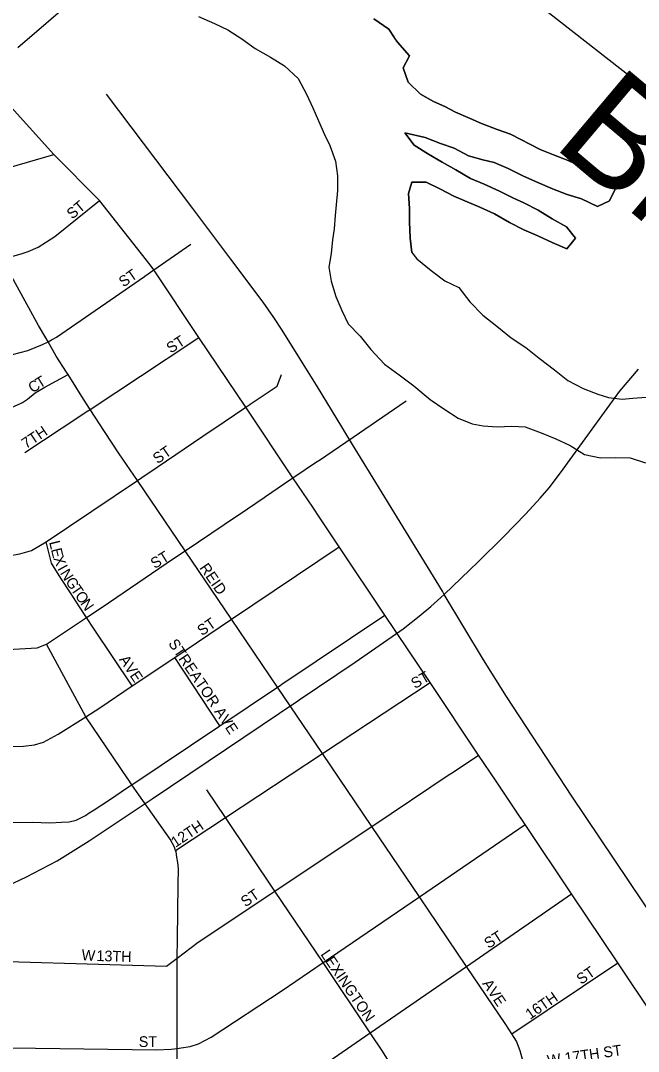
# Model space of a CAD drawing. Extents: x 1857828 to 2277390, y 930619 to 1324581.
# Drawn here: x 2056915 to 2059789, y 1259151 to 1263951 of the extents above; entities that cross this region are included whole.
import ezdxf

# ---------------------------------------------------------------- set-up
doc = ezdxf.new("R2010")
doc.units = 0
for name, color, linetype in [('GM_X_City_Street', 7, 'Continuous'), ('GM_X_City_Street_Text', 7, 'Continuous'), ('GM_X_Major_River', 7, 'Continuous'), ('GM_X_Major_River_Text', 7, 'Continuous'), ('GM_X_Rail_Line', 7, 'Continuous'), ('GM_X_State_Route', 7, 'Continuous'), ('GM_X_US_Route', 7, 'Continuous')]:
    doc.layers.add(name, color=color, linetype=linetype)

msp = doc.modelspace()

# ---------------------------------------------------------------- linework, layer by layer
at = {"layer": 'GM_X_City_Street'}
for points in [[(2059086.9, 1264216.1), (2059087.3, 1264215.5), (2059153.5, 1264159.2), (2059376.6, 1263984.3), (2059751.9, 1263690), (2059876.4, 1263597.3), (2059954.7, 1263538.9), (2060077.1, 1263456.3), (2060129.3, 1263422.1), (2060183.6, 1263393.9), (2060273.4, 1263350.3), (2060273.8, 1263350.1)], [(2055989.9, 1263027.2), (2056183.8, 1263079.8), (2056461.4, 1263154.4), (2056652.3, 1263205.7), (2057069.3, 1263328.1)], [(2056292.4, 1262694.8), (2056470.2, 1262742.4), (2056829.7, 1262840.3), (2056918.1, 1262865.4), (2056950.2, 1262875.4), (2056996.4, 1262895.4), (2057074.8, 1262945.4), (2057281.8, 1263113.8)], [(2057493.4, 1262761.4), (2057534.3, 1262789.7), (2057706.9, 1262909.2)], [(2059252.9, 1259102), (2059238.9, 1259154.2), (2059222.8, 1259198.5), (2059200.7, 1259233.1), (2059172.6, 1259276.9), (2058989.7, 1259547.1), (2058770.2, 1259871.4), (2058548.7, 1260198.6), (2058318.9, 1260538.1), (2058110, 1260846.7), (2057895.6, 1261163.5), (2057680.1, 1261481.7), (2057458.3, 1261809.5), (2057373.8, 1261934.3), (2057305.5, 1262036.9), (2057238, 1262140.4), (2057207.1, 1262187.8), (2057136.1, 1262302.7), (2057128.8, 1262314.5), (2057080.7, 1262388.9), (2057042.4, 1262455.9), (2057032.5, 1262473.4), (2056998.3, 1262531.7), (2056829.7, 1262840.3)], [(2057065, 1262467.7), (2057081.9, 1262476.5), (2057491.4, 1262760), (2057493.4, 1262761.4)], [(2056564, 1262347.1), (2056584.6, 1262352), (2056635.5, 1262359.7), (2056689.8, 1262373.3), (2056719.9, 1262379.1), (2056752.1, 1262384.8), (2056796.3, 1262386.5), (2056842.4, 1262390.1), (2056876.6, 1262395.8), (2056949, 1262415.3), (2057017.4, 1262442.9), (2057042.4, 1262455.9), (2057058.8, 1262464.5), (2057065, 1262467.7)], [(2057592.8, 1262374.7), (2057601.7, 1262380.6), (2057744.8, 1262475.1)], [(2057194.6, 1262111.7), (2057220, 1262128.5), (2057238, 1262140.4), (2057592.8, 1262374.7)], [(2056923.7, 1262173), (2056947.6, 1262188.8), (2056983.4, 1262217.3), (2057027.3, 1262243.8), (2057136.1, 1262302.7)], [(2057982.6, 1262164.3), (2058108, 1262249.1), (2058128.4, 1262303.2)], [(2058300.2, 1261901.2), (2058462.9, 1262011.2), (2058708.3, 1262180.5)], [(2056442.5, 1262046.7), (2056657.1, 1262096.3), (2056858.3, 1262142.9), (2056918, 1262169.2), (2056923.7, 1262173)], [(2057809.3, 1262047), (2057962.1, 1262150.4), (2057980.9, 1262163.2), (2057982.6, 1262164.3)], [(2056933.8, 1261939.4), (2057194.6, 1262111.7)], [(2057506.1, 1261841.9), (2057805.7, 1262044.6), (2057809.3, 1262047)], [(2058177.3, 1261818.1), (2058182.3, 1261821.4), (2058297, 1261899.1), (2058300.2, 1261901.2)], [(2056523.8, 1261401.7), (2056703.5, 1261432.3), (2056796.3, 1261448.2), (2056910.6, 1261467.2), (2056965.6, 1261484.1), (2057034.3, 1261523.4), (2057458.3, 1261809.5), (2057499, 1261837), (2057506.1, 1261841.9)], [(2058054.4, 1261734.9), (2058172.7, 1261814.9), (2058177.3, 1261818.1)], [(2057931.5, 1261651.8), (2058048.3, 1261730.8), (2058054.4, 1261734.9)], [(2057603.8, 1261430.1), (2057680.1, 1261481.7), (2057923.9, 1261646.7), (2057931.5, 1261651.8)], [(2057434.7, 1260852.6), (2057254.7, 1261121.5), (2057221.5, 1261172.1), (2057189.4, 1261221.3), (2057146.5, 1261287.1), (2057101.6, 1261355), (2057058.7, 1261424.8), (2057034.3, 1261523.4)], [(2056528.7, 1260576.5), (2056837.8, 1260571.2), (2056928, 1260572.1), (2056980.1, 1260578.6), (2057022.1, 1260591.1), (2057089.8, 1260627.9), (2057217.8, 1260709), (2057283, 1260750.3), (2057434.7, 1260852.6), (2057632, 1260985.7), (2057895.6, 1261163.5), (2058396.5, 1261501.3)], [(2056438.3, 1261010.8), (2056519.2, 1261012.2), (2056800.3, 1261018.7), (2056991.7, 1261030.6), (2057036, 1261048), (2057221.5, 1261172.1), (2057293.9, 1261220.4), (2057592.3, 1261422.3), (2057603.8, 1261430.1)], [(2058130.4, 1260860.4), (2058610.3, 1261181.8)], [(2057414.9, 1260419.1), (2057414.4, 1260419.8), (2057217.8, 1260709), (2057036, 1261048)], [(2057841.3, 1260666.8), (2057632, 1260985.7)], [(2057432.3, 1260392.8), (2057432.6, 1260393), (2057841.3, 1260666.8), (2058110, 1260846.7), (2058122.2, 1260854.9), (2058130.4, 1260860.4)], [(2057635.9, 1260087.2), (2057867.7, 1260240.3), (2058318.9, 1260538.1), (2058819.8, 1260868.8)], [(2058918.1, 1260445.5), (2059045.9, 1260530.9)], [(2057644.1, 1259175.2), (2057644, 1259176.9), (2057643.4, 1259445), (2057644, 1259585.4), (2057644.4, 1259676), (2057647.5, 1259929), (2057649.8, 1260001.3), (2057645.9, 1260031.4), (2057642, 1260055.6), (2057638.1, 1260081.7), (2057635.9, 1260087.2), (2057630.2, 1260101.8), (2057610.3, 1260140.1), (2057464.7, 1260345.8), (2057432.6, 1260393), (2057414.9, 1260419.1)], [(2058108.6, 1259904.4), (2058548.7, 1260198.6), (2058914.1, 1260442.9), (2058918.1, 1260445.5)], [(2057257.4, 1260276.5), (2057328, 1260323), (2057412.3, 1260379.5), (2057432.3, 1260392.8)], [(2058668.6, 1258968.7), (2058662.8, 1259010.8), (2058660.5, 1259032.8), (2058650.2, 1259056.9), (2058633.7, 1259094.9), (2058599, 1259152.7), (2058541.7, 1259237.8), (2058321.9, 1259564.8), (2058098.2, 1259897.5), (2057867.7, 1260240.3), (2057780.8, 1260369.7)], [(2056536.6, 1260215.7), (2056970.2, 1260219.1), (2057050.4, 1260215.9), (2057104.6, 1260218.4), (2057140.7, 1260220.7), (2057172.7, 1260227.1), (2057216.6, 1260249.6), (2057234.4, 1260261.4), (2057257.4, 1260276.5)], [(2054886.5, 1259203.5), (2055664.1, 1259184.9), (2056466.8, 1259165.8), (2056534.8, 1259172.1), (2057545.9, 1259158.4), (2057616.1, 1259161.1), (2057644.1, 1259165), (2057662.2, 1259167.6), (2057704.2, 1259174), (2057742.2, 1259186.5), (2057802, 1259217.2), (2058132.4, 1259435.3), (2058321.9, 1259564.8), (2058770.2, 1259871.4), (2059262.2, 1260207.8)], [(2056536.3, 1259578.3), (2057594.1, 1259547.7), (2057644, 1259585.4), (2057741.4, 1259659), (2058079.6, 1259885), (2058098.2, 1259897.5), (2058108.6, 1259904.4)], [(2058024.2, 1258880.5), (2058541.7, 1259237.8), (2058989.7, 1259547.1), (2059478.5, 1259884.5)], [(2059200.7, 1259233.1), (2059693.2, 1259563.6)], [(2057646.2, 1258282.5), (2057646.2, 1258283.1), (2057646, 1258384.2), (2057645, 1258760.1), (2057644.9, 1258830.3), (2057644.1, 1259165), (2057644.1, 1259175.2)]]:
    msp.add_lwpolyline(points, dxfattribs=at)
at = {"layer": 'GM_X_Major_River'}
for points in [[(2057742.6, 1263969.3), (2057817.2, 1263937.6), (2057879.7, 1263907.9), (2057944.3, 1263866.2), (2058006.9, 1263820.4), (2058077.5, 1263780.7), (2058142.1, 1263740.9), (2058206.8, 1263681.1), (2058245.6, 1263609), (2058274.2, 1263544.9), (2058300.9, 1263484.8), (2058329.5, 1263420.8), (2058354.1, 1263368.7), (2058380.8, 1263296.6), (2058389.4, 1263228.3), (2058390, 1263160), (2058382.5, 1263093.6), (2058378.9, 1263043.4), (2058373.4, 1262981.1), (2058365.8, 1262930.8), (2058360.3, 1262866.4), (2058348.8, 1262802.1), (2058359.4, 1262737.9), (2058382.1, 1262665.7), (2058408.8, 1262601.6), (2058439.4, 1262539.5), (2058494.1, 1262481.6), (2058544.8, 1262419.7), (2058607.6, 1262351.8), (2058676.3, 1262302), (2058745, 1262250.3), (2058819.8, 1262186.5), (2058884.5, 1262142.7), (2058951.1, 1262099), (2059015.6, 1262073.3), (2059067.8, 1262063.6), (2059132.1, 1262060), (2059200.3, 1262062.5), (2059262.6, 1262058.9), (2059337.1, 1262031.3), (2059405.6, 1262003.6), (2059472.1, 1261971.9), (2059538.8, 1261930.2), (2059613.2, 1261914.6), (2059681.4, 1261917.1), (2059751.7, 1261915.6), (2059822.1, 1261891.9)], [(2057742.6, 1263969.3), (2057817.2, 1263937.6), (2057879.7, 1263907.9), (2057944.3, 1263866.2), (2058006.9, 1263820.4), (2058077.5, 1263780.7), (2058142.1, 1263740.9), (2058206.8, 1263681.1), (2058245.6, 1263609), (2058274.2, 1263544.9), (2058300.9, 1263484.8), (2058329.5, 1263420.8), (2058354.1, 1263368.7), (2058380.8, 1263296.6), (2058389.4, 1263228.3), (2058390, 1263160), (2058382.5, 1263093.6), (2058378.9, 1263043.4), (2058373.4, 1262981.1), (2058365.8, 1262930.8), (2058360.3, 1262866.4), (2058348.8, 1262802.1), (2058359.4, 1262737.9), (2058382.1, 1262665.7), (2058408.8, 1262601.6), (2058439.4, 1262539.5), (2058494.1, 1262481.6), (2058544.8, 1262419.7), (2058607.6, 1262351.8), (2058676.3, 1262302), (2058745, 1262250.3), (2058819.8, 1262186.5), (2058884.5, 1262142.7), (2058951.1, 1262099), (2059015.6, 1262073.3), (2059067.8, 1262063.6), (2059132.1, 1262060), (2059200.3, 1262062.5), (2059262.6, 1262058.9), (2059337.1, 1262031.3), (2059405.6, 1262003.6), (2059472.1, 1261971.9), (2059538.8, 1261930.2), (2059613.2, 1261914.6), (2059681.4, 1261917.1), (2059751.7, 1261915.6), (2059822.1, 1261891.9)], [(2058557.8, 1263958.7), (2058628.5, 1263911), (2058654.6, 1263870.1)], [(2058654.6, 1263870.1), (2058628.5, 1263911), (2058557.8, 1263958.7)], [(2058653.8, 1263871.2), (2058669.2, 1263851), (2058723.9, 1263787.1), (2058694.3, 1263730.6), (2058718.9, 1263664.5), (2058775.6, 1263608.6), (2058836.1, 1263574.9), (2058888.5, 1263551.1), (2058938.9, 1263525.3), (2059007.4, 1263495.7), (2059059.8, 1263471.9), (2059132.4, 1263444.3), (2059194.8, 1263422.6), (2059331.9, 1263351.2), (2059394.4, 1263325.5), (2059462.8, 1263299.9), (2059525.3, 1263270.2), (2059593.8, 1263242.5), (2059658.2, 1263224.9), (2059684.8, 1263172.8), (2059655.1, 1263112.3), (2059599.2, 1263085.8), (2059524.6, 1263121.5), (2059458.2, 1263141.1), (2059389.7, 1263166.8), (2059321.2, 1263196.4), (2059254.7, 1263226.1), (2059184.1, 1263261.8), (2059117.6, 1263289.5), (2059065.3, 1263303.2), (2058998.9, 1263320.8), (2058932.3, 1263356.6), (2058867.9, 1263378.2), (2058797.4, 1263405.9), (2058702.9, 1263427.9)], [(2058702.8, 1263427.9), (2058797.4, 1263405.9), (2058867.9, 1263378.2), (2058932.3, 1263356.6), (2058998.9, 1263320.8), (2059065.3, 1263303.2), (2059117.6, 1263289.5), (2059184.1, 1263261.8), (2059254.7, 1263226.1), (2059321.2, 1263196.4), (2059389.7, 1263166.8), (2059458.2, 1263141.1), (2059524.6, 1263121.5), (2059599.2, 1263085.8), (2059655.1, 1263112.3), (2059684.8, 1263172.8), (2059658.2, 1263224.9), (2059593.8, 1263242.5), (2059525.3, 1263270.2), (2059462.8, 1263299.9), (2059394.4, 1263325.5), (2059331.9, 1263351.2), (2059194.8, 1263422.6), (2059132.4, 1263444.3), (2059059.8, 1263471.9), (2059007.4, 1263495.7), (2058938.9, 1263525.3), (2058888.5, 1263551.1), (2058836.1, 1263574.9), (2058775.6, 1263608.6), (2058718.9, 1263664.5), (2058694.3, 1263730.6), (2058723.9, 1263787.1), (2058669.2, 1263851), (2058654.6, 1263870.1)], [(2058702.5, 1263428.4), (2058745.5, 1263371.3), (2058812.1, 1263329.6), (2058876.7, 1263291.9), (2058939.2, 1263256.1), (2059007.8, 1263216.4), (2059072.3, 1263188.7), (2059142.8, 1263157.1), (2059205.3, 1263125.3), (2059255.7, 1263101.6), (2059322.3, 1263067.9), (2059388.9, 1263028.1), (2059455.4, 1262990.4), (2059496, 1262938.5), (2059456.3, 1262888), (2059387.8, 1262917.6), (2059321.3, 1262949.3), (2059256.8, 1262977), (2059190.3, 1263010.7), (2059119.7, 1263050.4), (2059051.1, 1263082.1), (2058982.6, 1263111.8), (2058930.2, 1263133.5), (2058865.7, 1263167.2), (2058801.2, 1263198.9), (2058734.9, 1263198.5), (2058719.3, 1263146.1), (2058723.9, 1263075.9), (2058724.5, 1263013.6), (2058727.1, 1262937.3), (2058735.7, 1262871)], [(2058735.7, 1262871), (2058727.1, 1262937.3), (2058724.5, 1263013.6), (2058723.9, 1263075.9), (2058719.3, 1263146.1), (2058734.9, 1263198.5), (2058801.2, 1263198.9), (2058865.7, 1263167.2), (2058930.2, 1263133.5), (2058982.6, 1263111.8), (2059051.1, 1263082.1), (2059119.7, 1263050.4), (2059190.3, 1263010.7), (2059256.8, 1262977), (2059321.3, 1262949.3), (2059387.8, 1262917.6), (2059456.3, 1262888), (2059496, 1262938.5), (2059455.4, 1262990.4), (2059388.9, 1263028.1), (2059322.3, 1263067.9), (2059255.7, 1263101.6), (2059205.3, 1263125.3), (2059142.8, 1263157.1), (2059072.3, 1263188.7), (2059007.8, 1263216.4), (2058939.2, 1263256.1), (2058876.7, 1263291.9), (2058812.1, 1263329.6), (2058745.5, 1263371.3), (2058702.8, 1263427.9)], [(2058735.7, 1262871), (2058758.1, 1262841), (2058824.8, 1262787.2), (2058889.4, 1262739.5), (2058953.9, 1262707.8), (2059004.7, 1262641.8), (2059065.4, 1262579.9), (2059130.1, 1262528.1), (2059196.8, 1262474.3), (2059265.5, 1262428.6), (2059328.1, 1262378.8), (2059398.9, 1262325), (2059461.5, 1262275.2), (2059532.1, 1262237.5), (2059600.6, 1262211.9), (2059650.9, 1262196.1), (2059713.2, 1262188.5), (2059763.4, 1262192.9), (2059825.6, 1262197.3)]]:
    msp.add_lwpolyline(points, dxfattribs=at)
at = {"layer": 'GM_X_Rail_Line'}
for points in [[(2058409.3, 1262058.8), (2058296.3, 1262244.9), (2058132.2, 1262509.4), (2058093.9, 1262568.4), (2058043.1, 1262640.4), (2057892.6, 1262840), (2057716.1, 1263076.1), (2057314.7, 1263609.1)], [(2058886.4, 1261278.1), (2059043.1, 1261430.6), (2059162.3, 1261547.9), (2059266.3, 1261654), (2059331.9, 1261726.5), (2059373.5, 1261775.1), (2059426.3, 1261844.9), (2059700.9, 1262224.6), (2059790, 1262328.6)], [(2058886.4, 1261278.1), (2058877.2, 1261293.4), (2058442.1, 1262004.7), (2058409.3, 1262058.8)], [(2058694.4, 1261119.2), (2058768.8, 1261177.5), (2058823, 1261222.9), (2058886.4, 1261278.1)], [(2061314.4, 1257602.6), (2060612.8, 1258655.7), (2060016.3, 1259538.1), (2059810.1, 1259847), (2059479.1, 1260339.1), (2059175.5, 1260803.7), (2059069.3, 1260974.5), (2058886.4, 1261278.1)], [(2058210.4, 1260788.1), (2058471.7, 1260963.6), (2058679.9, 1261107.9)], [(2058679.9, 1261107.9), (2058694.4, 1261119.2)], [(2058204.4, 1260784), (2058210.4, 1260788.1)], [(2044683.2, 1256198.2), (2047003.1, 1256900.8), (2049235, 1257574.5), (2049628.9, 1257694.6), (2049728.7, 1257726.8), (2049921.1, 1257796), (2050159.4, 1257869.2), (2051356.3, 1258230.8), (2052847.1, 1258678.3), (2055337.6, 1259437.3), (2056506.8, 1259789.8), (2056581.8, 1259814.4), (2056641.8, 1259834.5), (2056714.6, 1259862.5), (2056780.4, 1259889.1), (2056853.9, 1259922.2), (2056942.1, 1259963.8), (2057085.6, 1260039.1), (2057160.2, 1260084.6), (2057233.4, 1260130.8), (2057527, 1260327), (2057787.1, 1260503.3), (2058204.4, 1260784)]]:
    msp.add_lwpolyline(points, dxfattribs=at)
at = {"layer": 'GM_X_State_Route'}
for points in [[(2058306.8, 1261635.4), (2058273.9, 1261684.6), (2058182.3, 1261821.4), (2057962.1, 1262150.4), (2057744.8, 1262475.1), (2057534.3, 1262789.7), (2057517.9, 1262814.2), (2057281.8, 1263113.8), (2057069.3, 1263328.1), (2056742.7, 1263688.5)], [(2059217.4, 1260274.7), (2059127, 1260409.8), (2059045.9, 1260530.9), (2058819.8, 1260868.8), (2058610.3, 1261181.8), (2058396.5, 1261501.3), (2058306.8, 1261635.4)], [(2060079.7, 1257578.7), (2060038.3, 1257901.1), (2059992.8, 1258255.3), (2059950.7, 1258583.6), (2059879.7, 1259136.5), (2059878.9, 1259143.9), (2059860.8, 1259302.7), (2059859.4, 1259315.3), (2059693.2, 1259563.6), (2059478.5, 1259884.5), (2059262.2, 1260207.8), (2059217.4, 1260274.7)]]:
    msp.add_lwpolyline(points, dxfattribs=at)
at = {"layer": 'GM_X_US_Route'}
msp.add_lwpolyline([(2056901.4, 1263825.5), (2057176.7, 1264063.2), (2057712, 1264468.6), (2057722.3, 1264476.4)], dxfattribs=at)

# ---------------------------------------------------------------- texts
at = {"layer": 'GM_X_City_Street_Text'}
for s, rotation, p in [('ST', 39.8181, (2057155.1, 1263023.9)), ('ST', 34.7021, (2057393.4, 1262707.6)), ('ST', 32.7431, (2057613.6, 1262399.8)), ('C', 33.3129, (2056971, 1262214.8)), ('T', 31.4464, (2057003.8, 1262236.4)), ('7TH', 33.6901, (2056940.3, 1261955.3)), ('ST', 34.6873, (2057551.8, 1261884.8)), ('L', 283.9037, (2057047.2, 1261522.5)), ('E', 283.9037, (2057055.6, 1261488.3)), ('X', 290.4734, (2057066, 1261448.2)), ('ST', 31.5925, (2057539, 1261396.7)), ('I', 299.2098, (2057084.8, 1261399.4)), ('REID', 304.6965, (2057745.2, 1261402.8)), ('N', 301.5287, (2057096.7, 1261378.3)), ('G', 304.3453, (2057121.2, 1261338.5)), ('T', 304.4492, (2057146, 1261302.1)), ('O', 304.4297, (2057165.9, 1261273.1)), ('N', 304.4397, (2057190.8, 1261236.8)), ('ST', 34.7021, (2057758.6, 1261084)), ('STREATOR AVE', 303.9963, (2057600.1, 1261050.7)), ('AVE', 303.6922, (2057371.4, 1260975.9)), ('ST', 29.755, (2058749.3, 1260838)), ('12TH', 33.6975, (2057635.5, 1260098.5)), ('ST', 34.6794, (2057961, 1259821.2)), ('ST', 32.721, (2059092, 1259627.8)), ('W', 355.6039, (2057197, 1259576.4)), ('13TH', 358.2112, (2057267, 1259572.1)), ('LEXINGTON', 304.2881, (2058308.5, 1259603.2)), ('ST', 34.7021, (2059523, 1259460.4)), ('AVE', 303.6859, (2059061, 1259466.7)), ('16TH', 34.7021, (2059285.4, 1259297.6)), ('ST', 0, (2057464.7, 1259171.7)), ('W 17TH ST', 8.2424, (2059368.9, 1259083.6))]:
    msp.add_text(s, height=50, rotation=rotation, dxfattribs=at).set_placement(p)
at = {"layer": 'GM_X_Major_River_Text'}
msp.add_text('Black', height=500.3, rotation=319.8891, dxfattribs=at).set_placement((2059382.7, 1263371.9))

doc.saveas('drawing.dxf')
